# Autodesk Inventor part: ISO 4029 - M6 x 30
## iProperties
Comments: To add or edit properties for Autodesk Inventor files, use iProperties.
Created: 2004-08
Part Number: ISO 4029 - M6 x 30
Vendor: Autodesk Inc.
Document SubType Name: Modeling
Designer: John Blackburn
Material: Default
Description: Hexagon Socket Set Screw
Standard: ISO 4029
Size Designation: M6 x 30
Alert: To add or edit properties for Autodesk Inventor files, use iProperties.
Control State: 0
Master: False
Checked Out: False
Shininess: 64.0
Length Units: 11269
Angle Units: 11279
Time Units: 11290
Mass Units: 11283
Length Display Precision: 3
Angle Display Precision: 2
Compacted: True
EGR: 1
Density: 0.0
Volumn: 0.0
Area: 0.0
PropertySet Name: Model Information
Author: John Blackburn
Revision Number: 8
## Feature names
1. Body [Revolution]
2. Slot [Extrusion]
3. Chamfer1
4. Chamfer2
